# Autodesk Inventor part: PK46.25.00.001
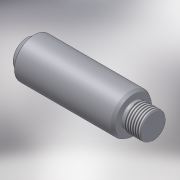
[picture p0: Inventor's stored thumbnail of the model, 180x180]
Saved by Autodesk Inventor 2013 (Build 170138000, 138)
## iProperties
Created: 2005-05
Part Number: PK46.25.00.001
Material: Steel, Mild
Document SubType Name: Modeling
Designer: PVitaliy
Manufacturer: Standard
Standards Organization: Custom
Density: 7.86 g/cm^3
Author: PVitaliy
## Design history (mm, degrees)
sketch "Эскиз2"
  geometry: L1 (0, 0)-(95.139, 0); L2 (0, 0)-(0, 27.494); L3 (0, 27.494)-(13, 35); L4 (13, 35)-(15, 35); L5 (15, 35)-(15, 40); L6 (15, 40)-(209, 40); L7 (209, 40)-(215, 36.536); L8 (215, 36.536)-(215, 24.5); L9 (215, 24.5)-(221, 24.5); L10 (221, 24.5)-(222.5, 26); L11 (222.5, 26)-(255, 26); L12 (255, 26)-(255, 0); L13 (255, 0)-(0, 0)
  constraints: 26 end point, 6 horizontal, 4 vertical, 1 other
  dimensions: "d0" = 70 diameter of L4 L1; "d1" = 30 deg angle of L3 L4; "d2" = 15 distance between parallel lines of L5 L2; "d3" = 2 distance of L3.end L4.end; "d4" = 80 diameter of L6 L1; "d5" = 200 distance between parallel lines of L8 L5; "d6" = 30 deg angle of L6 L7; "d7" = 6 horizontal distance of L6.end L7.end; "d8" = 255 distance between parallel lines of L12 L2; "d9" = 52 diameter of L11 L1; "d10" = 6 distance of L8.end L9.end; "d11" = 49 diameter of L9 L1; "d12" = 45 deg angle of L10 L9
revolve "Вращение1" sketch "Эскиз2" stored, may be unused: angle "d13" = 90 deg
feature "Резьба1" dims "d14" = 10, "d15" = 0
chamfer "Фаска1" distance "d16" = 1.6; stored, may be unused: second distance "d17" = 2, angle "d18" = 45 deg
fillet "Сопряжение1" dims "d19" = 1, "d20" = 0.5
body "Solid1"
